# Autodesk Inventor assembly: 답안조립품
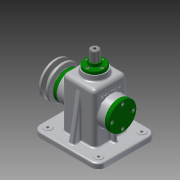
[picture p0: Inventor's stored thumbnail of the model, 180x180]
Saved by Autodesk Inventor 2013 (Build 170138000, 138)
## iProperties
Created: 2016-01
Part Number: 답안조립품
Document SubType Name: Assembly
Designer: Administrator
Author: Administrator
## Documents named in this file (19)
- C:\Users\Administrator\Desktop\460127V1013\답안조립품.iam
- C:\Users\Administrator\Desktop\460127V1013\1본체.ipt
- C:\Users\Administrator\Desktop\460127V1013\V-벨트풀리.ipt
- C:\Users\Administrator\Desktop\460127V1013\고정핀.ipt
- C:\Users\Administrator\Desktop\460127V1013\뒤커버.ipt
- C:\Users\Administrator\Desktop\460127V1013\링크.ipt
- C:\Users\Administrator\Desktop\460127V1013\멈춤링 6 x 5.ipt
- C:\Users\Administrator\Desktop\460127V1013\멈춤링 15 x 1.ipt
- C:\Users\Administrator\Desktop\460127V1013\베어링 15 x 35 x 11.ipt
- C:\Users\Administrator\Desktop\460127V1013\볼트 M3 x 8.ipt
- C:\Users\Administrator\Desktop\460127V1013\볼트 M4 x 10.ipt
- C:\Users\Administrator\Desktop\460127V1013\볼트 M6 x 12.ipt
- C:\Users\Administrator\Desktop\460127V1013\상부부시.ipt
- C:\Users\Administrator\Desktop\460127V1013\슬라이드바.ipt
- C:\Users\Administrator\Desktop\460127V1013\앞커버.ipt
- C:\Users\Administrator\Desktop\460127V1013\오일실 15 25 7.ipt
- C:\Users\Administrator\Desktop\460127V1013\와셔.ipt
- C:\Users\Administrator\Desktop\460127V1013\키 5 x 5 x 14.ipt
- C:\Users\Administrator\Desktop\460127V1013\편심축.ipt
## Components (16 placed, 6 different names)
1. 1본체:1
2. V-벨트풀리:1 — 각도:2
3. 고정핀:1
4. ISO 4018 M6 x 12:1
5. ISO 4762 M4 x 10:2
6. ISO 4762 M4 x 10:3
7. ISO 4762 M4 x 10:4
8. ISO 4762 M4 x 10:5
9. ISO 4762 M4 x 10:1
10. ISO 4762 M4 x 10:6
11. ISO 4762 M4 x 10:7
12. ISO 4762 M4 x 10:8
13. ISO 4762 M3 x 8:1
14. ISO 4762 M3 x 8:2
15. ISO 4762 M3 x 8:3
16. ISO 4762 M3 x 8:4
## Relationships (1: Angle 1)
- 각도:2 [Angle]: V-벨트풀리:1
